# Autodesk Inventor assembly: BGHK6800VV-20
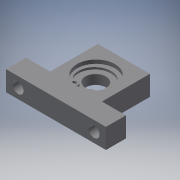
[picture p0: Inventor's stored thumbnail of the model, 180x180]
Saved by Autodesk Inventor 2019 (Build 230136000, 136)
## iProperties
Category: PARTsolutions
Company: MISUMI
Created: 2022-11
Part Number: BGHK6800VV-20
Catalog Web Link: www.cadenas.de
Description: BGHKB, BGHK, BGHKA, BGHKSA, BGHKS-Bearings with Housings T-Shaped h Selectable
Vendor: MISUMI
Document SubType Name: Assembly
Designer: psAdmin
Manufacturer: MISUMI
Mass: 9.17909 g
Surface Area: 56.1194 cm^2
Volume: 9.17909 cm^3
Density: 1 g/cm^3
Title: BGHK6800VV-20
Author: Cadenas PARTsolutions
Comments: Bearings with Housings T-Shaped h Selectable
PSOL_IDENT_0: {$CADENAS_DATA/23d-libs/misumi/metric/12_bearing_holders/bghkb_asmtab.prj},241 {VTYP=3D},{STYP=ASSTA
PSOL_IDENT_1: B},{NB=BGHK6800VV-20},{LINA=BGHK6800VV-20},{NN=BGHKB, BGHK, BGHKA, BGHKSA, BGHKS},{DATE=30.06.2021 1
PSOL_IDENT_2: 2:58:11},{GEOMDATE=09.07.2015 08:06:15},{VERSION=},{LINEID=300},{WBVAR=MATB,MATH,STH,SEAL,HH,ALT1,AL
PSOL_IDENT_3: T2},{WBNUMERIC=HH}  {NB=BGHK6800VV-20},{LINA=BGHK6800VV-20},{KT=DUMMY},{PN=BGHK6800VV-20},{TYPE=BGHK
PSOL_IDENT_4: },{MATB=S},{MATBALG='S','Steel','SS','Stainless Steel'},{MATH=S45C},{MATHALG='S45C','1045 Carbon Ste
PSOL_IDENT_5: el','2017AA','2017 Aluminum Alloy'},{STH=ENP},{STHALG='BO','Black Oxide','ENP','Electroless Nickel P
PSOL_IDENT_6: lating'},{ARR=304 Stainless Steel},{ARR3D=-S},{BN=6800},{SEAL=VV},{SEALALG='ZZ','Double Shielded','V
PSOL_IDENT_7: V','Non-Contact Sealed Rubber Seal','DD','Contact Sealed Rubber Seal'},{HH=20},{HHALG=[20,25,30]},{D
PSOL_IDENT_8: D=10},{D=19},{DD2=20},{MM=1.15},{DDHH=16},{B=5},{LL1=2},{H=34},{H2=14},{L=50},{L1=38.0},{L2=26},{T=1
PSOL_IDENT_9: 0},{S=10},{DD1=5.5},{ALT1=},{ALT2=},{PPATH=bghkb/bghkb_asmtpl.prj}
NB: BGHK6800VV-20
NN: BGHKB, BGHK, BGHKA, BGHKSA, BGHKS
NT: Bearings with Housings T-Shaped h Selectable
NBSYN: $PN.
LINA: BGHK6800VV-20
CATALOG: Misumi
PN: BGHK6800VV-20
MATB: Steel
MATH: 1045 Carbon Steel
STH: Electroless Nickel Plating
ARR: 304 Stainless Steel
BN: 6800
SEAL: Non-Contact Sealed Rubber Seal
HH: 20
DD: 10
D: 19
DDHH: 16
B: 5
LL1: 2
H: 34
L: 50
L1: 38
L2: 26
T: 10
S: 10
DD1: 5.5
ALT1: Bearings, Retaining Rings Assembled
ALT2: w/o KCC (C2 Chamfer)
SUPPLIER: MISUMI
ARTICLENO: BGHK6800VV-20
BOMINFO: BGHK6800VV-20
CREATOR: CADENAS GmbH
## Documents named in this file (4)
- e:\temp\worker_COMMON_6\temp\tmp_3884_44_KbP5p\format_0\BGHK6800VV-20.iam
- e:\temp\worker_COMMON_6\temp\tmp_3884_44_KbP5p\format_0\BGHK6800VV-20_h.ipt
- e:\temp\worker_COMMON_6\temp\tmp_3884_44_KbP5p\format_0\bearing_6800.ipt
- e:\temp\worker_COMMON_6\temp\tmp_3884_44_KbP5p\format_0\RRING-C-INT-S-19.ipt
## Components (3 placed, 3 different names)
1. BGHK6800VV-20_h:1 — to_bearing_XY@1 <-> to_housing_XY@2, to_bearing_Z@1 <-> to_housing_Z@2, to_bearing_YZ@1 <-> to_housing_YZ@2, to_rring_XY@1 <-> rr_XY@3, to_rring_Z@1 <-> rr_Z@3, to_rring_YZ@1 <-> rr_YZ@3
2. bearing_6800:1 — to_bearing_XY@1 <-> to_housing_XY@2, to_bearing_Z@1 <-> to_housing_Z@2, to_bearing_YZ@1 <-> to_housing_YZ@2
3. RRING-C-INT-S-19:1 — to_rring_XY@1 <-> rr_XY@3, to_rring_Z@1 <-> rr_Z@3, to_rring_YZ@1 <-> rr_YZ@3
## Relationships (6: Mate 4, Angle 2)
- to_bearing_XY@1 <-> to_housing_XY@2 [Mate]: BGHK6800VV-20_h:1 ↔ bearing_6800:1
- to_bearing_Z@1 <-> to_housing_Z@2 [Mate]: BGHK6800VV-20_h:1 ↔ bearing_6800:1
- to_bearing_YZ@1 <-> to_housing_YZ@2 [Angle]: BGHK6800VV-20_h:1 ↔ bearing_6800:1
- to_rring_XY@1 <-> rr_XY@3 [Mate]: BGHK6800VV-20_h:1 ↔ RRING-C-INT-S-19:1
- to_rring_Z@1 <-> rr_Z@3 [Mate]: BGHK6800VV-20_h:1 ↔ RRING-C-INT-S-19:1
- to_rring_YZ@1 <-> rr_YZ@3 [Angle]: BGHK6800VV-20_h:1 ↔ RRING-C-INT-S-19:1
